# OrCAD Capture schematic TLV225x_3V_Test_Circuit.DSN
size A; title: TLV225x, TLV225xA Advanced LinCMOS RAIL-TO-RAIL VERY; rev: 1.1; note: Datasheet: SLOS185D EVM: N/A
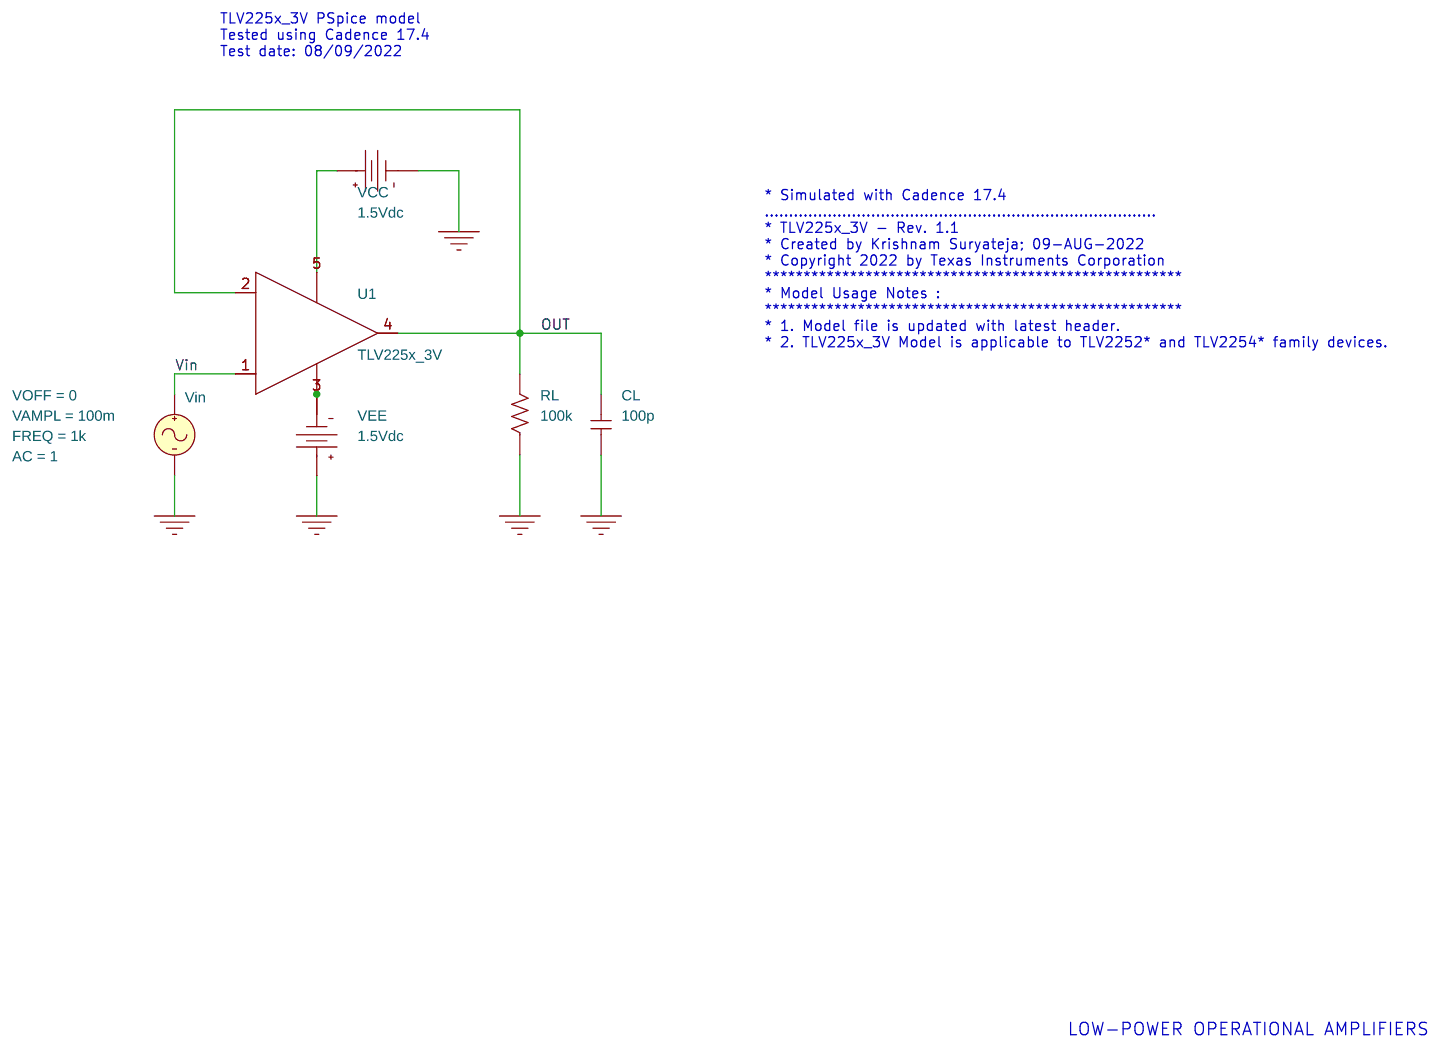
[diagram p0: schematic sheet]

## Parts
CL  100p  [RAD/CK05]
RL  100k  [AX/RC05]
U1  TLV225x_3V
VCC  VDC
VEE  VDC
Vin  VSIN

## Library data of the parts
CL = C
RL = R
U1 = TLV225x_3V
VCC VEE = VDC: DC: 1.5Vdc
Vin = VSIN: AC: 1; FREQ: 1k; VAMPL: 100m; VOFF: 0

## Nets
Vin: U1.1(+) Vin.1(+)
0: CL.1 RL.1 VCC.1(-) VEE.0(+) Vin.2(-)
OUT: CL.2 RL.2 U1.2(-) U1.4(OUT)
N23001: U1.5(V+) VCC.0(+)
N23017: U1.3(V-) VEE.1(-)

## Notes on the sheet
- TLV225x_3V PSpice model
  Tested using Cadence 17.4
  Test date: 08/09/2022
- * Simulated with Cadence 17.4
  .................................................................................
  * TLV225x_3V - Rev. 1.1
  * Created by Krishnam Suryateja; 09-AUG-2022
  * Copyright 2022 by Texas Instruments Corporation
  ******************************************************
  * Model Usage Notes :
  ******************************************************
  * 1. Model file is updated with latest header.
  * 2. TLV225x_3V Model is applicable to TLV2252* and TLV2254* family devices.
- LOW-POWER OPERATIONAL AMPLIFIERS
